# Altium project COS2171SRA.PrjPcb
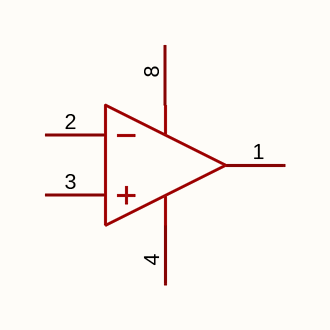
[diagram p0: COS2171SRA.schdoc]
1 sheet, 1 parts. Net scope: global (net labels, ports and power ports of the same name join across sheets).

## Sheet COS2171SRA.schdoc
size 127 x 101 mm

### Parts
U?  cos2171sra  [SOP-8_L4.9-W3.9-P1.27-LS6.0-BL]  (value not drawn)  (part A of 2)

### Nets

Not connected (* = marked no-connect by the designer): U? 1(OUT_A) 2(IN_A-) 3(IN_A+) 4(V-) 8(V+)

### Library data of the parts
U? = cos2171sra: 放大器数:2;轨到轨:轨到轨输入,轨到轨输出;增益带宽积(GBW):5MHz;输入失调电压(Vos):300uV;压摆率(SR):3V/us;输入偏置电流(Ib):10pA;; Manufacturer: COSINE(科山芯创); AddInBom: yes; ModelId: 75c24a7891ee4dd6bdac16a7163ff87e; ModelName: SOP-8_L4.9-W3.9-P1.27-LS6.0-BL-1; ModelTransform: 192.913,236.22,0,0,0,0,-0.393,2.749,0; Number of Channels: 2; Gain Bandwidth Product: 5MHz; Vos - Input Offset Voltage: 300uV; Input Offset Voltage Drift(Vos TC): 300nV/℃; Slew Rate: 3V/us; Ib - Input Bias Current: 10pA; Input Offset Current(Ios): 4pA; Input Voltage Noise Density: 18nV/√Hz@1kHz; Common Mode Rejection Ratio(CMRR): 120dB; Quiescent Current: 700uA; Output Current: 40mA; Single supply: 4.5V~40V; Dual Supply: 2.25V~20V；-20V~-2.25V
